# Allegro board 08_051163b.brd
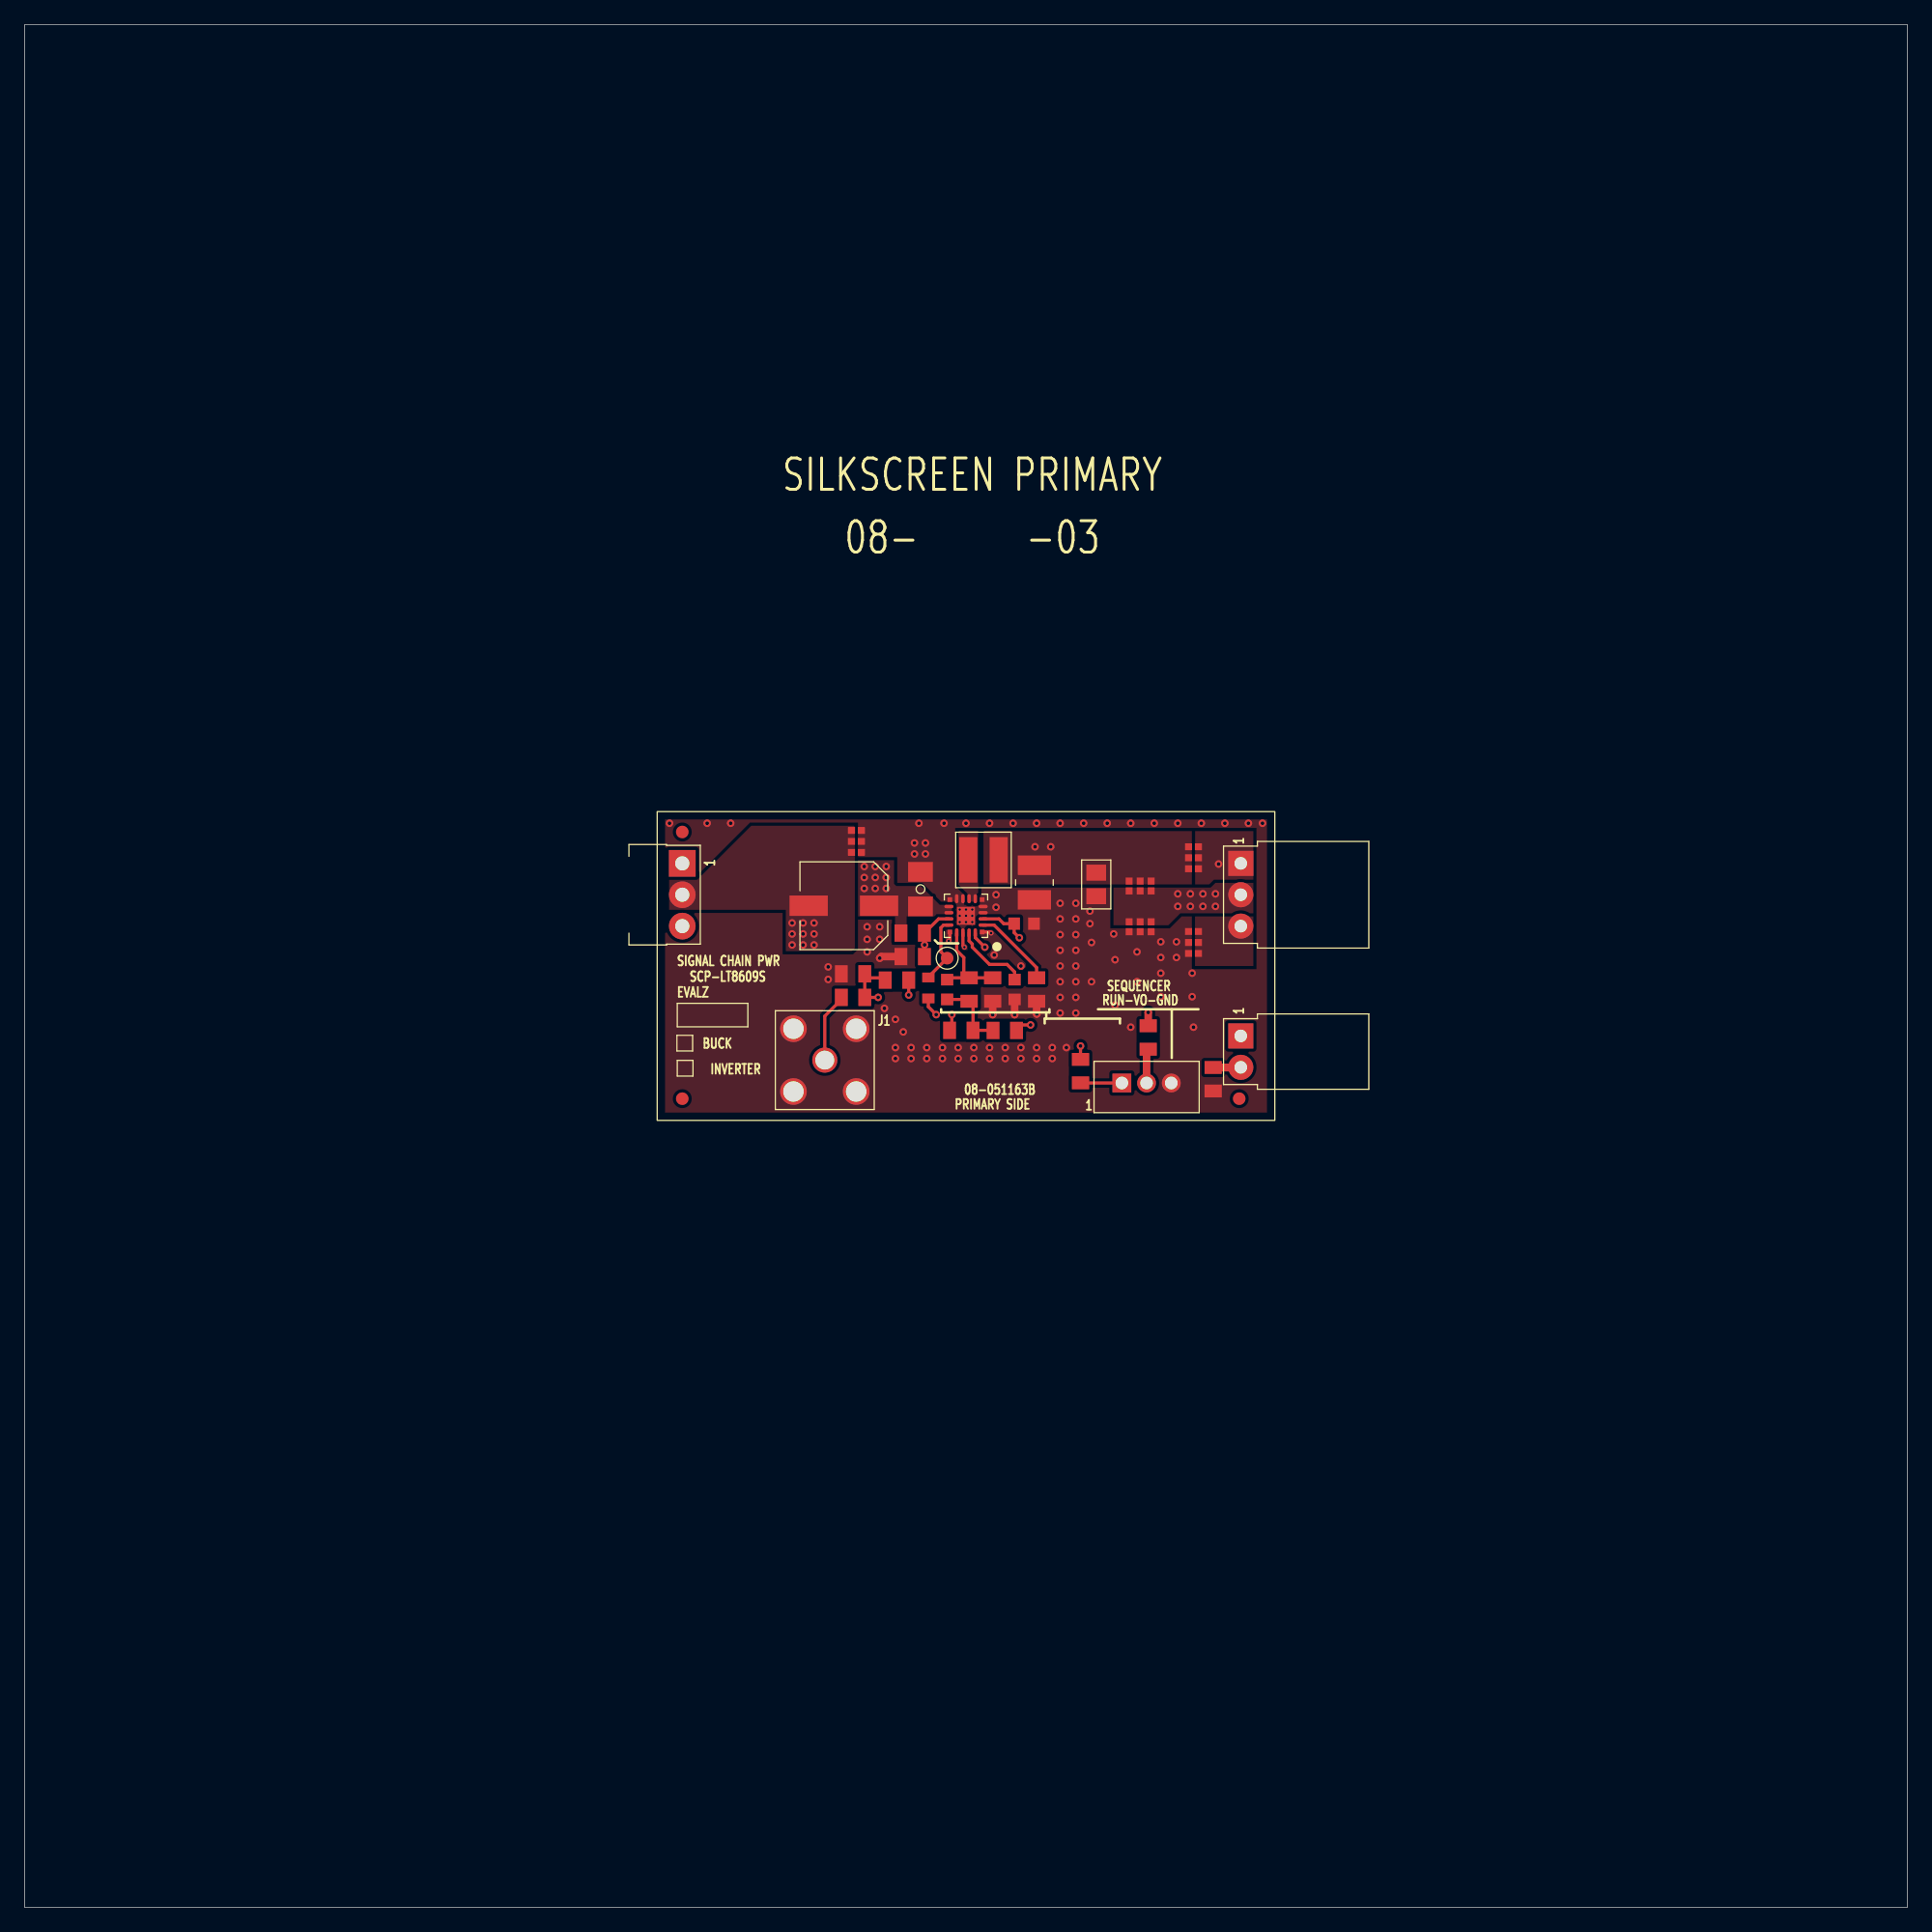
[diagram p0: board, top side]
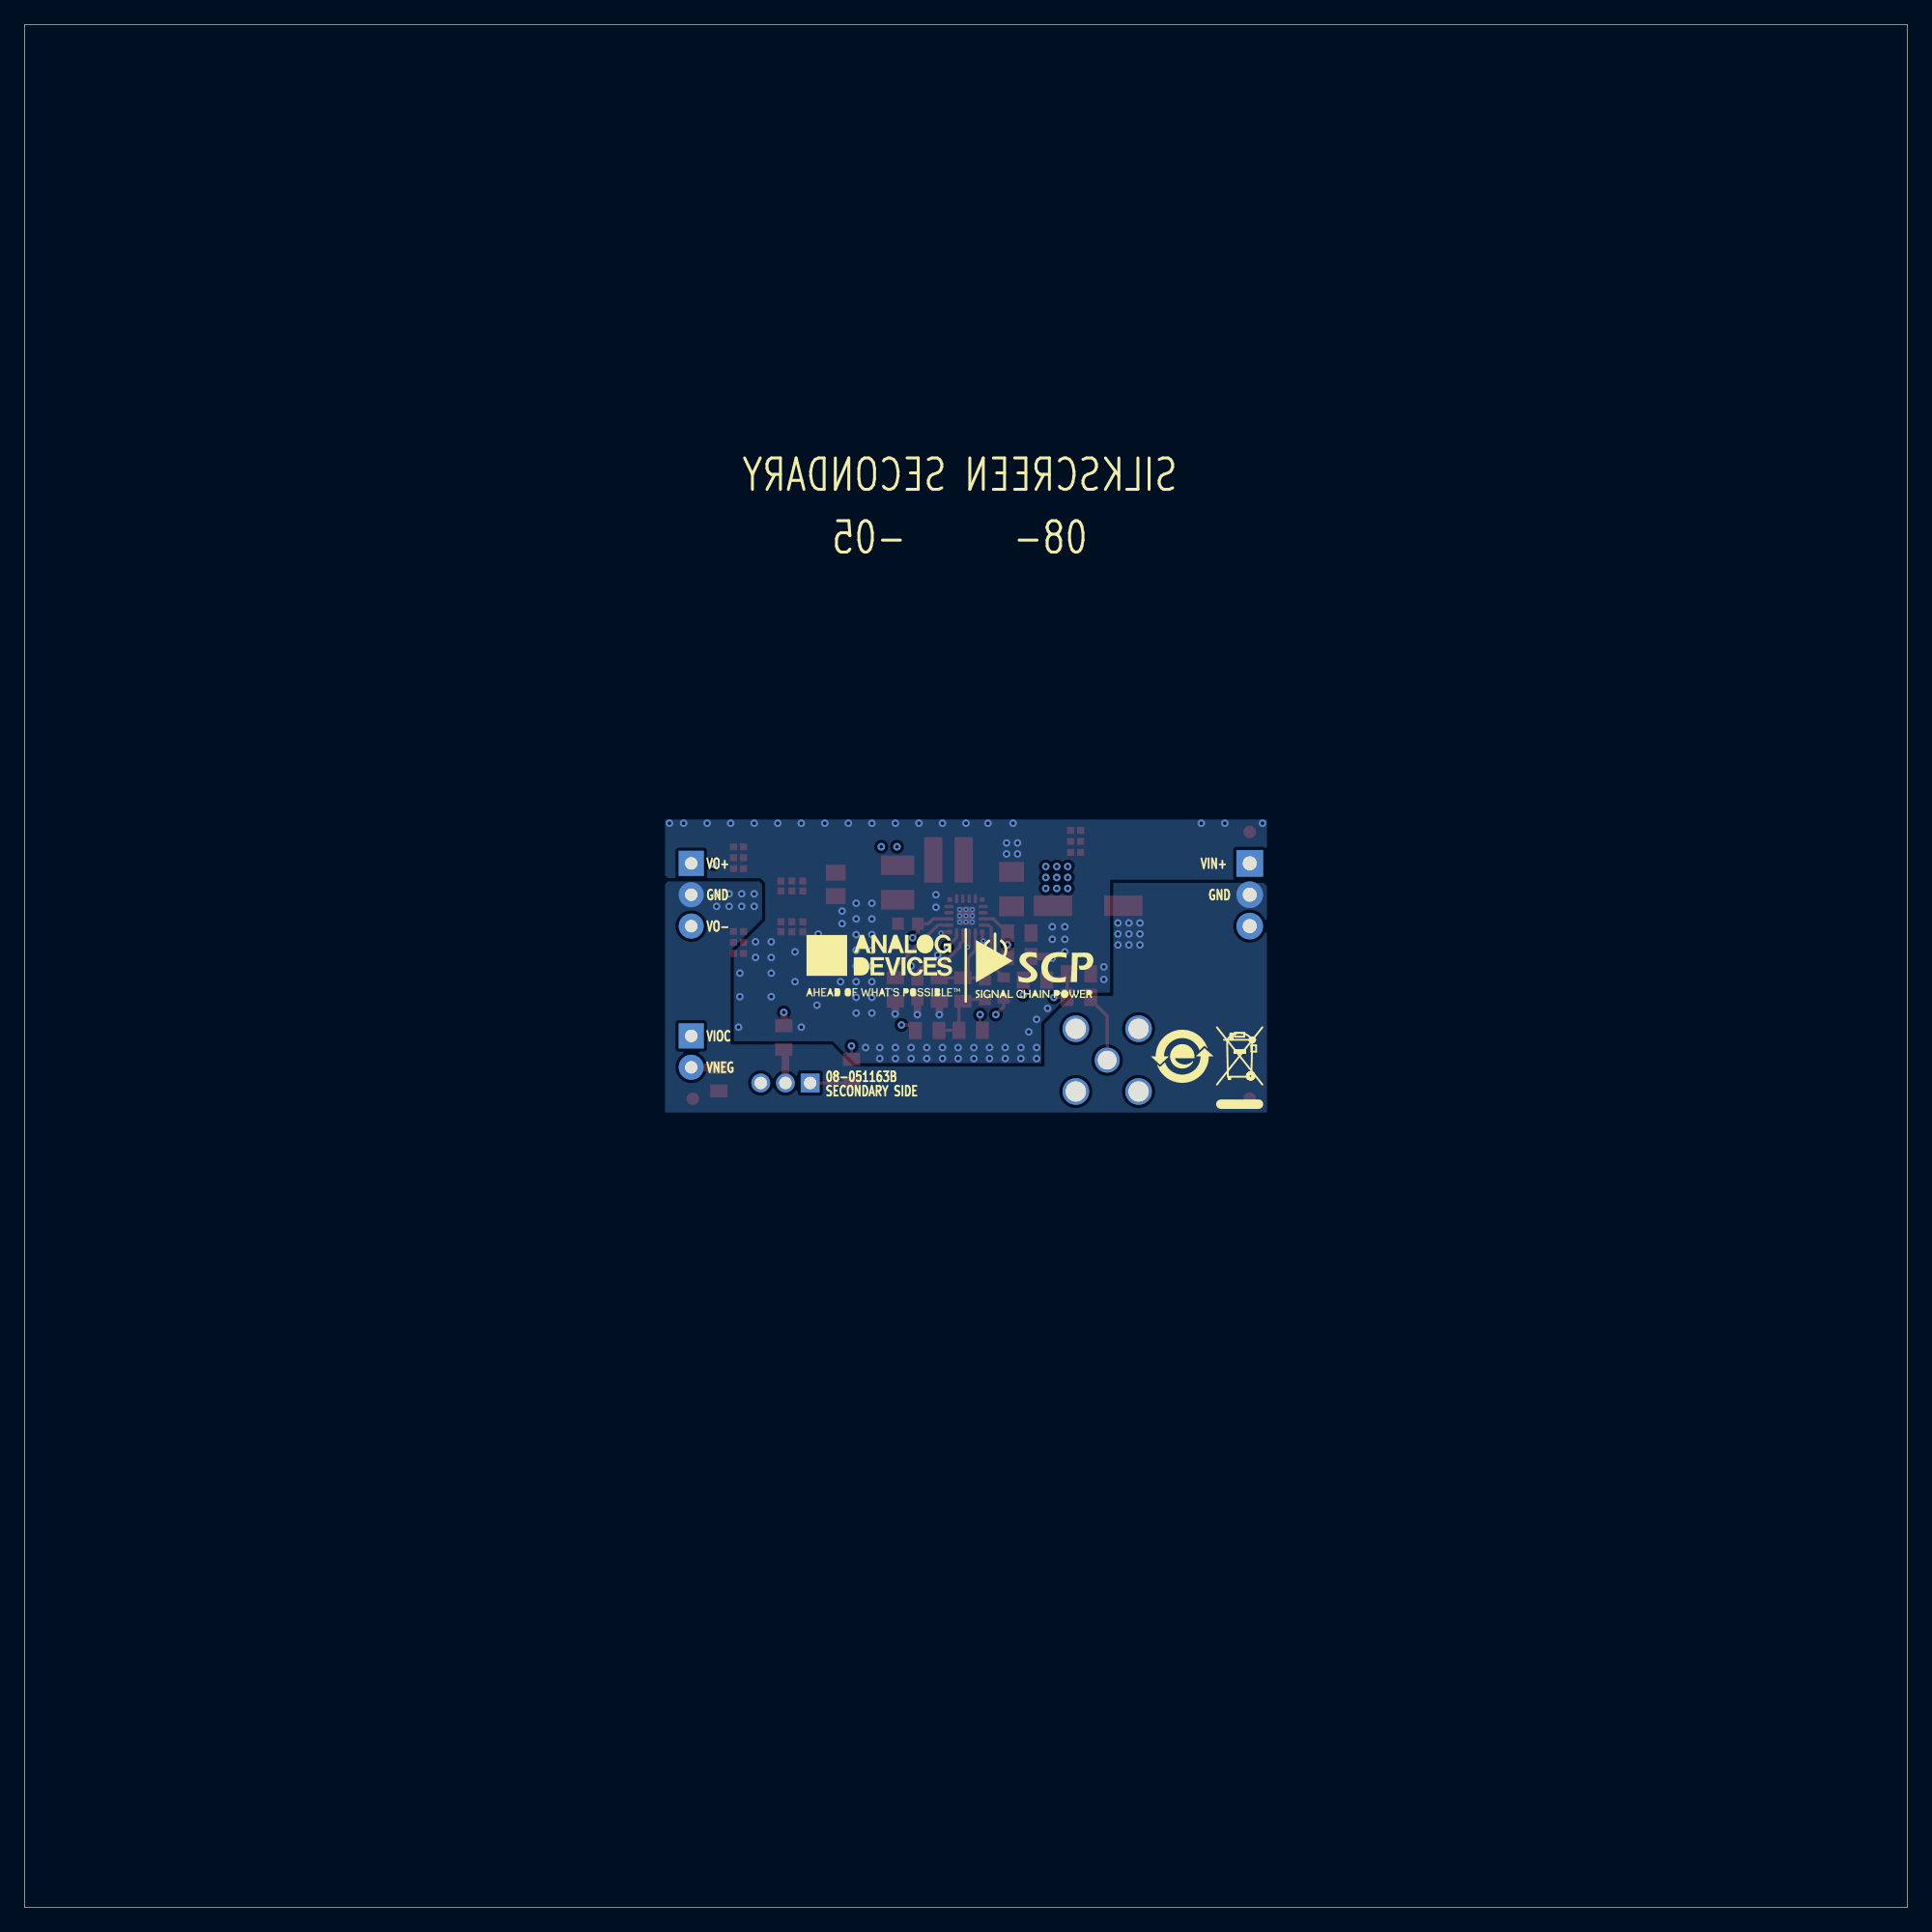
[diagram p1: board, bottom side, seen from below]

Outline 152.4 x 152.4 mm; copper layers: TOP, L2_GND, L3_SIG, BOTTOM. Coordinates in mm from the lower left corner of the outline.
Outline path: 0,152.4 152.4,152.4 152.4,0 0,0 0,152.4

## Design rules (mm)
constraint set DEFAULT: min track width 0.254

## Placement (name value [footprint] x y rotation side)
C1  22UF  [CPLSMSQ260H315]  66.31 81.08 180 top
C2  4.7UF  [C1206H71]  72.52 82.42 270 top
C4  1UF  [C0603]  80.9 79.63 180 top
C5  10pF  [C0603]  74.68 74.3 270 top
C6  47uF  [C1210-2]  81.74 82.96 270 top
C8  0.01uF  [C0603]  80.14 74.3 270 top
C9  4.7UF  [C0805H53]  86.74 82.8 270 top
INPUT  PBC03SBAN  [CNTHMHDRRA1X3L300W100H145]  53.23 84.51 270 top
L1  2.2uH  [LSMSQ157H83]  77.62 84.79 0 top
NOREF  -  []  76.71 109.73 0 top
NOREF#2  -  []  101.2 63.7 90 top
NOREF#3  -  []  101.2 63.7 90 top
NOREF#4  -  []  53.23 84.51 0 top
NOREF#5  -  [unnamed#2]  53.23 87.05 0 top
NOREF#6  -  []  133.24 266.25 0 top
NOREF#7  -  [unnamed#2]  98.32 65.46 0 top
NOREF#8  -  []  0.91 -105.74 0 top
NOREF#9  -  []  -298.45 -222.25 0 top
NOREF#10  -  []  51.2 63.7 0 top
NOREF#11  -  []  120.8 168.08 0 top
NOREF#12  -  []  101.2 88.7 180 top
NOREF#13  -  []  51.2 88.7 270 top
NOREF#14  -  [unnamed#2]  53.23 65.46 0 top
NOREF#15  -  []  51.2 88.7 0 top
NOREF#16  -  []  13.35 20.88 0 top
NOREF#17  -  []  53.23 84.51 0 top
NOREF#18  -  []  -298.45 -222.25 0 top
NOREF#19  -  []  51.2 88.7 0 top
NOREF#20  -  []  190.67 78.34 0 top
NOREF#21  -  []  51.2 88.7 0 top
NOREF#22  -  []  83.2 76.2 180 bottom
NOREF#23  -  []  58.69 68.89 180 bottom
NOREF#24  -  []  70.63 76.25 180 bottom
NOREF#25  -  []  54.25 64.7 180 bottom
OUTPUT  PPPC031LGBN-RC  [CNHDRRA1X3H108]  98.44 84.51 270 top
P1  53253-0370  [CNTHMHDR1X3L315W144H224]  88.82 66.73 0 top
PG  TESTPAD  [TPSMC40]  74.68 76.83 0 top
R1  1MEG  [R0805]  71.88 78.87 0 top
R2  18.2K  [R0805]  81.92 74.3 270 top
R3  49.9K  [R0603]  73.15 74.42 270 top
R4  1MEG  [R0805]  76.45 74.3 270 top
R5  182K  [R0805]  78.36 74.3 270 top
R6  TBD0805  [R0805]  71.88 76.96 0 top
R7  TBD0805  [R0805]  85.47 67.69 90 top
R8  0  [R0805]  67.06 75.56 0 top
R9  TBD0805  [R0805]  67.06 73.66 0 top
R10  TBD0805  [R0805]  70.61 75.06 0 top
R11  0  [R0805]  75.82 70.99 0 top
R12  TBD0805  [R0805]  90.95 70.41 90 top
R13  TBD0805  [R0805]  79.34 70.98 180 top
R14  0  [R0805]  96.21 67.03 90 top
R21  -  [NC0402L]  67.33 87.18 0 top
R22  -  [NC0402L]  67.33 86.29 0 top
R23  -  [NC0402L]  67.33 85.4 0 top
R24  -  [NC0402L]  94.62 77.22 0 top
R25  -  [NC0402L]  94.62 78.99 0 top
R26  -  [NC0402L]  94.62 78.11 0 top
R27  -  [NC0402L]  89.41 79.38 90 top
R28  -  [NC0402L]  90.3 79.38 90 top
R29  -  [NC0402L]  91.19 79.38 90 top
R30  -  [NC0402L]  91.19 82.68 90 top
R31  -  [NC0402L]  89.41 82.68 90 top
R32  -  [NC0402L]  90.3 82.68 90 top
R33  -  [NC0402L]  94.62 84.07 0 top
R34  -  [NC0402L]  94.62 84.96 0 top
R35  -  [NC0402L]  94.62 85.85 0 top
SYNC  5-1814832-1  [CNTYCO1814832]  64.77 68.58 0 top
U1  LT8609SEV#PB  [QFN16_3X3_PAD1_45X1_45]  76.2 80.26 90 top
VIOC  PPPC021LGBN-RC  [CNTHFHDRRA1X2L220W335H108]  98.44 70.54 270 top

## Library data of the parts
C1 = CAPP: Tolerance: 20; User Part Number: UPN; alternate symbols: (); part number: CAPP_SM-22UF,63V,20,E033596,CPLSMSQ260H315; tolerance: 20
C2 = CAP: Tolerance: 10; User Part Number: UPN; alternate symbols: (); part number: CAP_SM-4.7UF,50V,10,E026699,C1206H71; tolerance: 10
C4 = CAP: User Part Number: UPN; Tolerance: 10; alternate symbols: (); part number: CAP_SM-1UF,25V,10,E025743,C0603; tolerance: 10
C5 = CAP: User Part Number: UPN; Tolerance: 0.5pF; alternate symbols: (); part number: CAP_SM-10PF,50V,0.5PF,E016319,C0603; tolerance: 0.5pF
C6 = CAP: Tolerance: 10; User Part Number: UPN; alternate symbols: (); part number: CAP_SM-47UF,10V,10,E011546,C1210-2; tolerance: 10
C8 = CAP: User Part Number: UPN; Tolerance: 10; alternate symbols: (); part number: CAP_SM-0.01UF,50V,10,E018587,C0603; tolerance: 10
C9 = CAP: Tolerance: 10; User Part Number: UPN; alternate symbols: (); part number: CAP_SM-4.7UF,16V,10,E031879,C0805H53; tolerance: 10
INPUT = CN3P: Tolerance: N/A; User Part Number: UPN; alternate symbols: (CNTHMHDRRA1X3L300W100H145_SCP); part number: CN3P_TH-PBC03SBAN,E034137,CNTHMHDRRA1X3L300W100H145; tolerance: N/A
L1 = IND: User Part Number: UPN; Tolerance: 20; alternate symbols: (); part number: IND_SM-2.2UH,20,E016651,LSMSQ157H83; tolerance: 20
OUTPUT = CN3P: User Part Number: UPN; Tolerance: N/A; alternate symbols: (CNHDRRA1X3H108_SCP); part number: CN3P_TH-PPPC031LGBN-RC,E034111,CNHDRRA1X3H108; tolerance: N/A
P1 = CN3P: Tolerance: N/A; User Part Number: UPN; alternate symbols: (); part number: CN3P_TH-53253-0370,E033940,CNTHMHDR1X3L315W144H224; tolerance: N/A
PG = NCTESTPAD: Tolerance: N/A; User Part Number: UPN; alternate symbols: (); part number: NCTESTPAD_SM-TESTPAD,E019801,TPSMC40; tolerance: N/A
R1 R4 = RES: User Part Number: UPN; Tolerance: 1; alternate symbols: (R0805L); part number: RES_SM-1MEG,E003518,1/8W,1,R0805; tolerance: 1
R2 = RES: User Part Number: UPN; Tolerance: 1; alternate symbols: (R0805L); part number: RES_SM-18.2K,E020752,1/8W,1,R0805; tolerance: 1
R3 = RES: User Part Number: UPN; Tolerance: 1; alternate symbols: (R0603L); part number: RES_SM-49.9K,E022444,1/4W,1,R0603; tolerance: 1
R5 = RES: User Part Number: UPN; Tolerance: 1; alternate symbols: (R0805L); part number: RES_SM-182K,E014265,1/8W,1,R0805; tolerance: 1
R6 R7 R9 R10 R12 R13 = RES: User Part Number: UPN; alternate symbols: (R0805L); part number: RES_SM-TBD0805,E004051,TBD0805,TBD0805,R0805
R8 R11 R14 = RES: User Part Number: UPN; Tolerance: N/A; alternate symbols: (); part number: RES_SM-0,E030875,1/8W,N/A,R0805; tolerance: N/A
R21-R35 = NC2P: User Part Number: UPN; Tolerance: N/A; alternate symbols: (); part number: NC2P_SM-NC0402L,E033984,NC0402L; tolerance: N/A
SYNC = CNBNC5P: Tolerance: N/A; User Part Number: UPN; alternate symbols: (); part number: CNBNC5P_TH-5-1814832-1,E010606,CNTYCO1814832; tolerance: N/A
U1 = LINLT8609S: User Part Number: UPN; Tolerance: N/A; alternate symbols: (); part number: LINLT8609S_SM-LT8609SEV#PB,E029914,QFN16_3X3_PAD1_45X1_45; tolerance: N/A
VIOC = CN2P: Tolerance: N/A; User Part Number: UPN; alternate symbols: (CNTHFHDRRA1X2L220W335H108_SCP); part number: CN2P_TH-PPPC021LGBN-RC,E034113,CNTHFHDRRA1X2L220W335H108; tolerance: N/A

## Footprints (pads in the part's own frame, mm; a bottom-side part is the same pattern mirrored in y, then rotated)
C0603
  rect 0.94x0.991 smd: 1(-0.8,0) 2(0.8,0)
C0805H53
  rect 1.295x1.6 smd: 1(-0.953,0) 2(0.953,0)
C1206H71
  rect 1.6x2.007 smd: 1(-1.397,0) 2(1.397,0)
C1210-2
  rect 1.575x2.692 smd: 1(-1.397,0) 2(1.397,0)
CNHDRRA1X3H108
  rect 2.032x2.032 hole 1.016: 1(0,0)
  round 2.032 hole 1.016: 2(2.54,0) 3(5.08,0)
CNTHFHDRRA1X2L220W335H108
  rect 2.032x2.032 hole 1.016: 1(0,0)
  round 2.032 hole 1.016: 2(2.54,0)
CNTHMHDR1X3L315W144H224
  rect 1.524x1.524 hole 1.016: 1(0,0)
  round 1.524 hole 1.016: 2(2,0) 3(4,0)
CNTHMHDRRA1X3L300W100H145
  rect 2.159x2.159 hole 1.143: 1(0,0)
  round 2.159 hole 1.143: 2(2.54,0) 3(5.08,0)
CNTYCO1814832
  round 2.032 hole 1.524: 1(0,0)
  round 2.159 hole 1.651: 2(-2.54,2.54) 3(2.54,2.54) 4(2.54,-2.54) 5(-2.54,-2.54)
CPLSMSQ260H315
  rect 3.099x1.651 smd: N(2.85,0) P(-2.85,0)
LSMSQ157H83
  rect 1.473x3.683 smd: 1(-1.232,0) 2(1.232,0)
NC0402L
  rect 0.572x0.559 smd: 1(-0.4,0) 2(0.4,0)
QFN16_3X3_PAD1_45X1_45
  oval 0.279x0.737 smd: 1(-0.75,-1.383) 2(-0.25,-1.383) 3(0.25,-1.383) 4(0.75,-1.383) 9(0.75,1.383) 10(0.25,1.383) 11(-0.25,1.383) 12(-0.75,1.383)
  oval 0.737x0.279 smd: 5(1.383,-0.75) 6(1.383,-0.25) 7(1.383,0.25) 8(1.383,0.75) 13(-1.383,0.75) 14(-1.383,0.25) 15(-1.383,-0.25) 16(-1.383,-0.75)
  rect 0.381x0.381 smd: 17(-1.31,-1.31) 18(1.31,-1.31) 19(1.31,1.31) 20(-1.31,1.31)
  rect 1.448x1.448 smd: PAD(0,0)
R0603
  rect 0.787x0.991 smd: 1(-0.85,0) 2(0.85,0)
R0805
  rect 1.041x1.397 smd: 1(-0.95,0) 2(0.95,0)
TPSMC40
  round 1.016 smd: 1(0,0)
unnamed#2
  round 1.016 smd: (0,0)

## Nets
GND: C1.N(N2) INPUT.2 OUTPUT.2 R21.1 R22.1 R23.1 R27.2(N2) R28.2(N2) R29.2(N2) R30.1 R31.1 R32.1
PG: PG.1(N1) R3.1 U1.12
RUN: P1.1 R7.1
SYNC: R9.1 SYNC.1
UNNAMED_2_CAP_I2_N2: C4.2(N2) R10.2(N2) U1.2
UNNAMED_2_CAP_I8_N1: C5.1 R4.1 R5.1 U1.13
UNNAMED_2_CAP_I8_N2: C5.2(N2) R4.2(N2) R11.2(N2) R13.2(N2)
UNNAMED_2_CAP_I10_N1: C8.1 U1.15
UNNAMED_2_CAP_I21_N1: C6.1 C9.1 L1.2(N2) R3.2(N2) R11.1 R30.2(N2) R31.2(N2) R32.2(N2) R33.1 R34.1 R35.1
UNNAMED_2_CN2P_I63_N2: R14.2(N2) VIOC.2(N2)
UNNAMED_2_CN3P_I67_N2: P1.2 R12.1
UNNAMED_2_IND_I11_N1: L1.1 U1.5 U1.6
UNNAMED_2_LINLT8609S_I60_EN: R1.2(N2) R6.2(N2) R7.2(N2) U1.11
UNNAMED_2_LINLT8609S_I60_RT: R2.1 U1.1
UNNAMED_2_RES_I40_N2: R8.2(N2) R9.2(N2) R10.1 U1.16
V+: C1.P C2.2(N2) INPUT.1 R1.1 U1.9 U1.10(VIN_2)
VIOC: R13.1 VIOC.1
VNEG: C2.1 C4.1 C6.2(N2) C8.2(N2) C9.2(N2) P1.3(N3) R2.2(N2) R5.2(N2) R6.1 R8.1 R14.1 R21.2(N2) R22.2(N2) R23.2(N2) R24.1 R25.1 R26.1 R27.1 R28.1 R29.1 SYNC.2 SYNC.3 SYNC.4 SYNC.5(SH4) U1.3 U1.4 U1.7 U1.8 U1.14 U1.17 U1.18 U1.19 U1.20 U1.PAD
VO+: OUTPUT.1 R12.2(N2) R33.2(N2) R34.2(N2) R35.2(N2)
VO-: OUTPUT.3(N3) R24.2(N2) R25.2(N2) R26.2(N2)

Pads without a net: INPUT 3

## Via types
v1: diameter 0.61, hole 0.305, TOP to BOTTOM, 138 vias
v2: diameter 0.406, hole 0.203, TOP to BOTTOM, 12 vias

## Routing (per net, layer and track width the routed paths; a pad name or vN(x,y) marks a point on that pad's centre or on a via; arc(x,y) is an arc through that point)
GND:
  vias: v1(62.12,79.68) v1(62.12,78.79) v1(62.12,77.91) v1(63.01,79.68) v1(63.01,78.79) v1(63.01,77.91) v1(63.9,79.68) v1(63.9,78.79) v1(63.9,77.91) v1(93.34,82.04) v1(93.34,81.03) v1(94.36,82.04) v1(94.36,81.03) v1(95.38,82.04) v1(95.38,81.03) v1(96.39,82.04) v1(96.39,81.03)
PG: length 5.6
  TOP w0.254: R3.1 73.15,75.31 PG.1 74.17,77.34 74.17,79.3 74.38,79.51 U1.12
RUN: length 3.4
  TOP w0.254: P1.1 85.48,66.73 R7.1
SYNC: length 5.6
  TOP w0.254: SYNC.1 64.77,72.15 66.11,73.48 R9.1
UNNAMED_2_CAP_I2_N2: length 16.4
  TOP w0.254: R10.2 v1(71.56,73.85) ; v1(80.52,78.49) 80.1,78.91 C4.2 79.25,79.63 78.86,80.01 U1.2
  L3_SIG w0.254: v1(71.56,73.85) 73.53,75.82 78.36,75.82 80.52,77.98 v1(80.52,78.49)
UNNAMED_2_CAP_I8_N1: length 7.8
  TOP w0.254: R4.1 R5.1 ; R4.1 76.02,75.68 76.02,76.89 75.45,77.46 U1.13 ; R4.1 74.83,75.24 C5.1
UNNAMED_2_CAP_I8_N2: length 5.9
  TOP w0.254: R13.2 78.38,70.99 R11.2 76.77,73.03 R4.2 76.3,73.49 C5.2
UNNAMED_2_CAP_I10_N1: length 6.1
  TOP w0.254: U1.15 76.45,78.24 76.71,77.98 76.71,77.72 78.11,76.33 79.53,76.33 80.14,75.72 C8.1
UNNAMED_2_CAP_I21_N1: length 42
  TOP w0.254: R3.2 73.15,72.9 v1(73.79,72.26) ; R11.1 75.06,71.18 v1(75.06,72.26)
  L3_SIG w0.254: v1(81.79,85.85) 81.79,76.33 80.01,74.55 75.56,74.55 73.79,72.77 v1(73.79,72.26) ; v1(75.06,72.26) 75.06,72.64 75.95,73.53 80.52,73.53 83.06,76.07 v1(83.06,85.85)
UNNAMED_2_CN2P_I63_N2: length 2.2
  TOP w0.635: R14.2 98.43,67.98 VIOC.2
UNNAMED_2_CN3P_I67_N2: length 2.8
  TOP w0.61: P1.2 90.82,69.33 R12.1
UNNAMED_2_LINLT8609S_I60_EN: length 27.8
  TOP w0.254: U1.11 73.98,80.01 R1.2 72.83,77.93 v1(72.85,77.91) 72.83,77.9 R6.2 ; R7.2 v1(85.47,69.72)
  L3_SIG w0.254: v1(85.47,69.72) 84.84,70.36 73.15,70.36 70.36,73.15 70.36,75.43 v1(72.85,77.91)
UNNAMED_2_LINLT8609S_I60_RT: length 6.6
  TOP w0.254: R2.1 81.92,76.07 78.47,79.51 U1.1
UNNAMED_2_RES_I40_N2: length 19
  TOP w0.254: v1(69.09,73.66) R9.2 R8.2 68.33,75.24 69.48,75.24 R10.1 ; v1(77.72,77.72) 76.95,78.5 U1.16
  L3_SIG w0.254: v1(77.72,77.72) 76.33,79.12 72.52,79.12 69.09,75.69 v1(69.09,73.66)
V+:
  vias: v1(67.96,84.26) v1(67.96,83.37) v1(67.96,82.48) v1(68.85,84.26) v1(68.85,83.37) v1(68.85,82.48) v1(69.74,84.26) v1(69.74,83.37) v1(69.74,82.48)
VIOC: length 18.7
  TOP w0.254: v1(81.43,71.43) 80.73,71.43 R13.1
  L3_SIG w0.254: v1(81.43,71.43) 87.19,71.43 88.08,70.54 VIOC.1
VNEG: length 7.8
  TOP w0.254: U1.20 74.89,78.32 v2(74.8,78.23) ; v2(76.07,77.72) 75.95,77.85 U1.14 ; v2(78.23,78.87) 78.14,78.95 U1.17
  TOP w0.61: R2.2 81.92,72.34 v1(81.93,72.32) ; C8.2 v1(80.14,72.26) ; v1(69.22,76.83) 69.34,76.96 R6.1 ; R5.2 v1(78.36,72.26)
  vias: v1(52.2,87.76) v1(55.25,87.76) v1(57.15,87.76) v1(65.04,76.13) v1(65.04,75.11) v1(68.2,79.38) v1(68.2,78.36) v1(68.2,77.34) v1(69.22,79.38) v1(69.22,78.36) v1(69.6,72.77) v1(70.48,71.88) v1(70.48,69.6) v1(70.48,68.71) v1(71.12,70.87) v1(71.75,69.6) v1(71.75,68.71) v1(72.03,86.16) v1(72.03,85.27) v1(72.39,87.76) v1(72.92,86.16) v1(72.92,85.27) v1(73.03,69.6) v1(73.03,68.71) v1(74.3,69.6) v1(74.3,68.71) v1(74.42,87.76) v1(75.56,69.6) v1(75.56,68.71) v1(76.2,87.76) v1(76.84,69.6) v1(76.84,68.71) v1(78.11,87.76) v1(78.11,69.6) v1(78.11,68.71) v1(78.49,77.09) v1(78.63,81.97) v1(78.63,80.95) v1(79.38,69.6) v1(79.38,68.71) v1(80.01,87.76) v1(80.64,76.2) v1(80.64,69.6) v1(80.64,68.71) v1(81.92,87.76) v1(81.92,69.6) v1(81.92,68.71) v1(83.19,69.6) v1(83.19,68.71) v1(83.82,87.76) v1(83.82,81.28) v1(83.82,80.01) v1(83.82,78.74) v1(83.82,77.47) v1(83.82,76.2) v1(83.82,74.93) v1(83.82,73.66) v1(83.82,72.39) v1(84.33,69.6) v1(85.09,81.28) v1(85.09,80.01) v1(85.09,78.74) v1(85.09,77.47) v1(85.09,76.2) v1(85.09,74.93) v1(85.09,73.66) v1(85.09,72.39) v1(85.72,87.76) v1(86.23,80.64) v1(86.23,79.63) v1(86.36,78.11) v1(86.36,74.93) v1(87.63,87.76) v1(88.16,78.79) v1(88.27,76.71) v1(88.27,73.03) v1(89.53,87.76) v1(89.53,71.25) v1(90.04,77.34) v1(90.04,74.93) v1(91.44,87.76) v1(91.97,78.16) v1(91.97,76.89) v1(91.97,75.62) v1(91.97,73.71) v1(93.24,78.16) v1(93.24,76.89) v1(93.34,87.76) v1(94.51,75.62) v1(94.51,73.71) v1(94.62,71.25) v1(95.25,87.76) v1(97.16,87.76) v1(99.06,87.76) v1(100.2,87.76) v2(75.69,80.77) v2(75.69,80.26) v2(75.69,79.76) v2(76.2,80.77) v2(76.2,80.26) v2(76.2,79.76) v2(76.71,80.77) v2(76.71,80.26) v2(76.71,79.76)
VO+: length 17.9
  TOP w0.61: R12.2 v1(90.95,72.44)
  L3_SIG w0.61: v1(90.95,72.44) 90.95,73.26 90.93,73.28 90.93,82.93 92.46,84.45 v1(96.65,84.45)

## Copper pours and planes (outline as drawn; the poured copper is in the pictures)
GND on TOP: 96.39,82.93 99.46,82.93 99.46,80.47 93.55,80.47 92.58,79.5 88.14,79.5 88.14,82.55 96.01,82.55
GND on TOP: 52.17,80.75 52.17,83.19 54.45,83.19 58.82,87.56 67.2,87.56 67.2,77.65 66.95,77.4 61.61,77.4 61.61,80.75
GND on BOTTOM: 92.96,83.06 100.33,83.06 100.56,82.82 100.56,64.34 51.84,64.34 51.84,82.68 52.09,82.93 64.28,82.93 64.28,73.79 67.56,73.79 69.85,71.5 69.85,68.07 85.31,68.07 87.09,69.85 95.25,69.85 95.25,77.47 92.71,80.01 92.71,82.8
GND on L2_GND: 92.96,83.06 100.33,83.06 100.56,82.82 100.56,64.34 51.84,64.34 51.84,82.68 52.09,82.93 64.28,82.93 64.28,67.82 65.66,67.82 65.91,68.07 84.98,68.07 84.98,65.59 93.49,65.59 95.25,67.35 95.25,77.47 92.71,80.01 92.71,82.8
UNNAMED_2_CAP_I21_N1 on TOP: 94.49,87.12 94.49,82.8 77.63,82.8 77.61,82.82 77.61,87.12
UNNAMED_2_IND_I11_N1 on TOP: 77.06,82.02 77.06,81.41 76.3,81.41 76.3,82.07 75.58,82.78 75.58,87.12 77.18,87.12 77.18,82.14
V+ on TOP: 75.06,81.15 75.06,80.39 73.81,80.39 73.63,80.21 71.4,80.21 71.4,78.18 70.46,78.18 70.46,80.21 67.46,80.21 67.46,84.76 70.38,84.76 70.38,82.86 70.56,82.68 72.55,82.68 74.07,81.15
V+ on L3_SIG: 52.34,87.18 52.34,82.86 66.31,82.86 67.33,81.84 70.38,81.84 70.38,87.18
VNEG on TOP: 51.84,88.06 100.56,88.06 100.56,64.34 51.84,64.34 ; 12 cut-outs
VNEG on BOTTOM: 51.84,88.06 100.56,88.06 100.56,83.55 100.33,83.31 92.84,83.31 92.46,82.93 92.46,79.88 95,77.34 95,70.1 88.77,70.1 86.36,67.69 65.66,67.69 65.66,72.64 58.67,72.64 58.67,83.19 52.2,83.19 51.84,83.55
VNEG on L2_GND: 51.84,88.06 100.56,88.06 100.56,83.55 100.33,83.31 92.84,83.31 92.46,82.93 92.46,79.88 95,77.34 95,67.6 93.24,65.84 85.24,65.84 85.24,66.17 85.24,68.07 64.52,68.07 64.52,73.15 62.48,73.15 62.48,83.19 52.07,83.19 51.84,83.42
VNEG on L3_SIG: 51.84,88.06 100.56,88.06 100.56,64.34 51.84,64.34
VO+ on TOP: 94.74,87.12 99.46,87.12 99.46,83.19 96.27,83.19 95.88,82.8 94.74,82.8
VO- on TOP: 99.46,76.2 94.74,76.2 94.74,80.21 99.46,80.21

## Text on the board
Ref Des/Silkscreen Bottom: GND | VIN+ | 08-051163B | SECONDARY SIDE | VO+ | VO- | VIOC | VNEG
User.Comments: 5.    INSTALL SOLDER BLOB USING THE TABLE BELOW (SEE DETAIL A) | AND PLACE MARK ON TICK BOX IN THE PRIMARY SIDE. | SCALING FACTOR: 1:4 | 05-051163-01-B | BOM | 05-051163-02-B | DETAIL A | R21, R22, R23, R27, R28, R29, R33, R34, R35 | PARTS | R24, R25, R26, R30, R31, R32 | INVERTER | TICK BOX | BUCK
Ref Des/Silkscreen Top: SIGNAL CHAIN PWR | EVALZ | J1 | PRIMARY SIDE | 08-051163B | RUN-VO-GND | SEQUENCER | BUCK | SCP-LT8609S | INVERTER
PAGE_OUTLINE: B | AS PER ECR-086389 | 07MAY19 | J. VIERNES
DIMENSION: REF
User.15: PER IPC-4552 LATEST REVISION | 15.    THRU VIAS TO BE FILLED WITH SOLDERMASK. | SEE FAB NOTE 15 | DIA MAX
User.17: L2 GND | 08-      -07
User.18: L3 SIG | 08-      -08
User.45: FIGURE | SIZE | 8.0 | 12.0 | 40.0 | 45.0 | 60.0 | 65.0 | PLATED | FINISHED HOLES IN MILS | ALL UNITS ARE IN MILS | QTY | 12 | 138 | 8 | 3 | 1 | 4 | TOLERANCE/NOTES
